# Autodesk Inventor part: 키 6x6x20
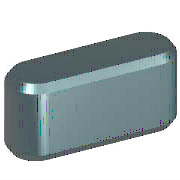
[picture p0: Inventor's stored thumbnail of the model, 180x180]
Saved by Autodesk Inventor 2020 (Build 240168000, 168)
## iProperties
Created: 2012-02
Part Number: 키 6x6x20
Material: 강철, 연강
Document SubType Name: Modeling
Standard: JIS B 1301
Designer: mdu-01
Standards Organization: JIS
Language: ko-KR
Size Designation: 6x6x20
Categories: <MemberInstance><Categories><Category DisplayName="샤프트 부품" InternalName="7f7aeb1f-a693-4053-b835-cee3144e0d98" Mnemonic="SHFT"><Category DisplayName="키" Interna
Density: 1 g/cm^3
Appearance: 티타늄
IsCustomPart: 1
Author: mdu-01
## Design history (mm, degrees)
workplane "Work Plane1"
workplane "Work Plane2"
sketch "스케치1"
  geometry: L1 (3, 3)-(17, 3); L2 (17, -3)-(3, -3); L3 (0, 9.4)-(0, -7.4) reference; L4 (-5, 0)-(30, 0) reference; L5 (20, 0)-(20, 7); A1 r 3 centre (3, 0) between (3, 3) and (3, -3); A2 r 3 centre (17, 0) between (17, -3) and (17, 3)
  constraints: 6 end point, 5 point on circle, 4 tangent, 3 point on line, 2 centre point, 1 horizontal, 1 parallel, 1 perpendicular
  dimensions: "d0" = 3 radius of A1 (= 0.5 x PB); "d13" = 3 radius of A2 (= 0.5 x PB); "d14" = 20 distance between parallel lines of L5 L3 (= NLG)
extrude "본체1" new body sketch "스케치1" taper "d3" = 0 deg; stored distance "d4" = 10
workplane "Work Plane3"
body "Solid1"
chamfer "모따기1" distance "d8" = 0.4 (= PHH); stored, may be unused: second distance "d9" = 0.4 (= PHH), angle "d15" = 45 deg
other parameters: "d1" = -3.5 (= -PNT), "d2" = 2.5 (= PH - PNT), "NLG" = 20 [user parameter; used in 3 equation terms], "PB" = 6 [user parameter; used in 2 equation terms], "PNT" = 3.5 [user parameter; used in 2 equation terms], "PH" = 6 [user parameter; used in 1 equation term], "PHH" = 0.4 [user parameter; used in 2 equation terms], "d10" = 0, "d16" = 0, "d17" = 0, "d18" = 0, "WDMIN" = 17 [user parameter], "WDMAX" = 22 [user parameter], "RR" = 0.16 [user parameter], "PUEB" = 2.8 [user parameter]
